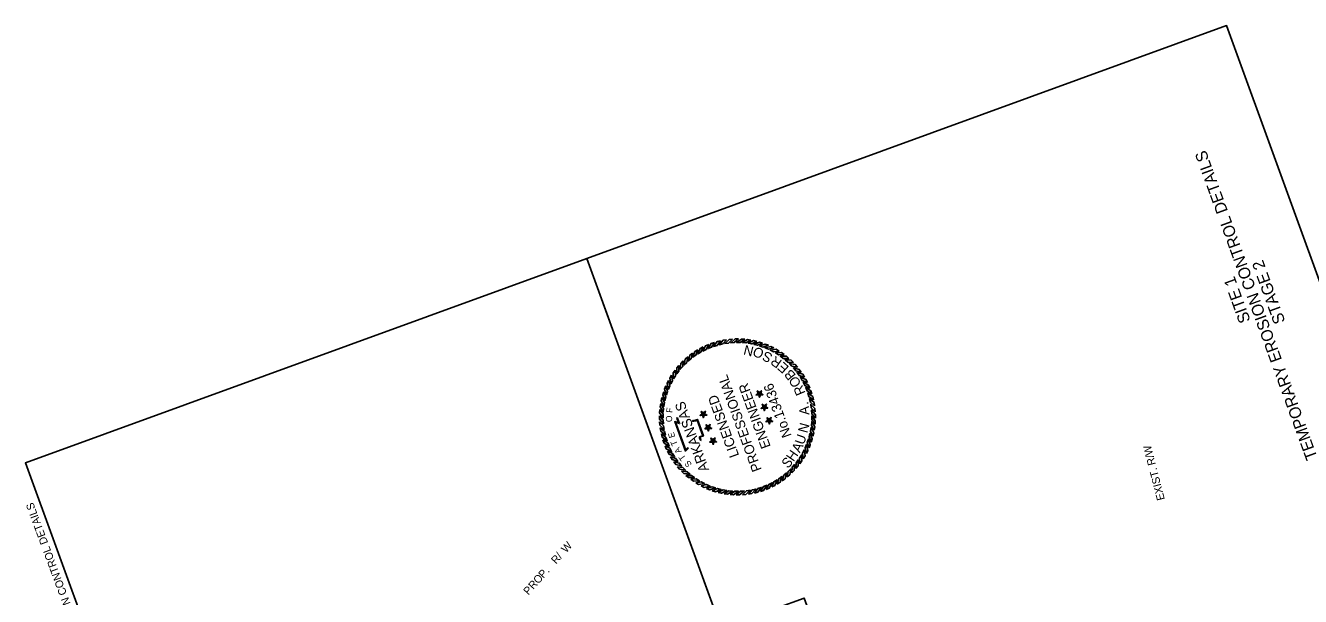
# Model space of a CAD drawing. Extents: x 986289 to 987754, y 1870781 to 1872971.
# Drawn here: x 986289 to 987265, y 1872534 to 1872971 of the extents above; entities that cross this region are included whole.
import ezdxf

# ---------------------------------------------------------------- set-up
doc = ezdxf.new("R2010")
doc.units = 0
for name, color, linetype in [('1', 7, 'Continuous'), ('60', 7, 'Continuous'), ('G-ANNO-SYMB', 7, 'Continuous'), ('NO PLOT', 7, 'Continuous'), ('R_Draft', 7, 'Continuous')]:
    doc.layers.add(name, color=color, linetype=linetype)

msp = doc.modelspace()

# ---------------------------------------------------------------- linework, layer by layer
at = {"layer": '1'}
msp.add_line((986821.23, 1872510.15), (986718.28, 1872792.99), dxfattribs=at)
at = {"layer": 'G-ANNO-SYMB'}
for points in [[(986820.6, 1872730.02), (986818.11, 1872729.41), (986815.39, 1872725.73), (986818.04, 1872726.56)], [(986825.21, 1872730.87), (986822.68, 1872730.45), (986819.68, 1872727), (986822.38, 1872727.61)], [(986829.87, 1872731.35), (986827.31, 1872731.13), (986824.05, 1872727.92), (986826.79, 1872728.32)], [(986834.55, 1872731.46), (986831.99, 1872731.44), (986828.48, 1872728.5), (986831.25, 1872728.69)], [(986839.23, 1872731.21), (986836.67, 1872731.39), (986832.95, 1872728.74), (986835.72, 1872728.7)], [(986843.87, 1872730.59), (986841.34, 1872730.97), (986837.42, 1872728.62), (986840.18, 1872728.36)], [(986848.45, 1872729.6), (986845.95, 1872730.19), (986841.86, 1872728.14), (986844.59, 1872727.68)], [(986799.32, 1872720.6), (986797.25, 1872719.07), (986796.14, 1872714.64), (986798.27, 1872716.41)], [(986803.25, 1872723.14), (986801.07, 1872721.78), (986799.62, 1872717.45), (986801.88, 1872719.05)], [(986807.37, 1872725.37), (986805.09, 1872724.19), (986803.31, 1872719.98), (986805.69, 1872721.4)], [(986811.65, 1872727.26), (986809.29, 1872726.27), (986807.18, 1872722.21), (986809.66, 1872723.44)], [(986816.07, 1872728.82), (986813.64, 1872728.01), (986811.22, 1872724.13), (986813.79, 1872725.16)], [(986852.94, 1872728.26), (986850.5, 1872729.04), (986846.26, 1872727.33), (986848.94, 1872726.65)], [(986857.31, 1872726.58), (986854.93, 1872727.54), (986850.57, 1872726.17), (986853.2, 1872725.28)], [(986861.54, 1872724.55), (986859.24, 1872725.7), (986854.79, 1872724.67), (986857.33, 1872723.58)], [(986865.59, 1872722.2), (986863.39, 1872723.53), (986858.87, 1872722.85), (986861.32, 1872721.56)], [(986869.44, 1872719.54), (986867.36, 1872721.03), (986862.8, 1872720.72), (986865.14, 1872719.24)], [(986788.88, 1872711.23), (986787.22, 1872709.27), (986787.18, 1872704.7), (986788.84, 1872706.92)], [(986792.11, 1872714.62), (986790.31, 1872712.8), (986789.91, 1872708.24), (986791.73, 1872710.33)], [(986795.59, 1872717.75), (986793.65, 1872716.07), (986792.9, 1872711.56), (986794.88, 1872713.5)], [(986873.08, 1872716.58), (986871.12, 1872718.24), (986866.54, 1872718.28), (986868.77, 1872716.62)], [(986876.47, 1872713.35), (986874.64, 1872715.16), (986870.09, 1872715.55), (986872.17, 1872713.73)], [(986879.6, 1872709.87), (986877.92, 1872711.81), (986873.41, 1872712.56), (986875.34, 1872710.58)], [(986783.26, 1872703.74), (986781.93, 1872701.55), (986782.61, 1872697.02), (986783.9, 1872699.48)], [(986785.92, 1872707.6), (986784.43, 1872705.51), (986784.75, 1872700.95), (986786.22, 1872703.3)], [(986882.44, 1872706.14), (986880.92, 1872708.21), (986876.48, 1872709.32), (986878.26, 1872707.19)], [(986884.98, 1872702.21), (986883.63, 1872704.39), (986879.29, 1872705.84), (986880.9, 1872703.58)], [(986887.21, 1872698.09), (986886.03, 1872700.37), (986881.82, 1872702.15), (986883.24, 1872699.77)], [(986777.2, 1872691.1), (986776.42, 1872688.65), (986778.13, 1872684.41), (986778.81, 1872687.1)], [(986778.89, 1872695.47), (986777.92, 1872693.09), (986779.29, 1872688.73), (986780.18, 1872691.35)], [(986780.91, 1872699.69), (986779.76, 1872697.4), (986780.79, 1872692.94), (986781.88, 1872695.49)], [(986850.53, 1872689.56), (986850.49, 1872690.6), (986848.85, 1872691.71), (986849.52, 1872689.84)], [(986850.53, 1872689.56), (986851.5, 1872689.91), (986852.05, 1872691.82), (986850.49, 1872690.6)], [(986889.11, 1872693.81), (986888.11, 1872696.17), (986884.06, 1872698.28), (986885.28, 1872695.8)], [(986890.66, 1872689.39), (986889.86, 1872691.82), (986885.98, 1872694.25), (986887.01, 1872691.67)], [(986774.88, 1872682.03), (986774.49, 1872679.49), (986776.85, 1872675.57), (986777.1, 1872678.33)], [(986775.86, 1872686.61), (986775.28, 1872684.11), (986777.32, 1872680.02), (986777.78, 1872682.75)], [(986850.53, 1872689.56), (986849.52, 1872689.84), (986847.96, 1872688.63), (986849.94, 1872688.69)], [(986850.53, 1872689.56), (986849.94, 1872688.69), (986850.62, 1872686.83), (986851.17, 1872688.74)], [(986850.53, 1872689.56), (986851.17, 1872688.74), (986853.15, 1872688.81), (986851.5, 1872689.91)], [(986854.26, 1872679.31), (986854.22, 1872680.35), (986852.58, 1872681.46), (986853.26, 1872679.59)], [(986854.26, 1872679.31), (986855.24, 1872679.66), (986855.78, 1872681.57), (986854.22, 1872680.35)], [(986891.87, 1872684.86), (986891.25, 1872687.35), (986887.58, 1872690.07), (986888.4, 1872687.42)], [(986892.71, 1872680.25), (986892.29, 1872682.78), (986888.84, 1872685.78), (986889.46, 1872683.08)], [(986893.19, 1872675.59), (986892.98, 1872678.15), (986889.77, 1872681.41), (986890.17, 1872678.67)], [(986774, 1872672.71), (986774.02, 1872670.14), (986776.96, 1872666.64), (986776.77, 1872669.4)], [(986774.26, 1872677.38), (986774.07, 1872674.82), (986776.73, 1872671.1), (986776.76, 1872673.87)], [(986807.6, 1872673.93), (986806.6, 1872674.22), (986805.04, 1872673), (986807.02, 1872673.07)], [(986807.6, 1872673.93), (986807.56, 1872674.97), (986805.92, 1872676.08), (986806.6, 1872674.22)], [(986807.6, 1872673.93), (986807.02, 1872673.07), (986807.69, 1872671.21), (986808.24, 1872673.11)], [(986807.6, 1872673.93), (986808.58, 1872674.29), (986809.12, 1872676.19), (986807.56, 1872674.97)], [(986807.6, 1872673.93), (986808.24, 1872673.11), (986810.22, 1872673.18), (986808.58, 1872674.29)], [(986854.26, 1872679.31), (986853.26, 1872679.59), (986851.69, 1872678.37), (986853.67, 1872678.44)], [(986854.26, 1872679.31), (986853.67, 1872678.44), (986854.35, 1872676.58), (986854.9, 1872678.49)], [(986854.26, 1872679.31), (986854.9, 1872678.49), (986856.88, 1872678.55), (986855.24, 1872679.66)], [(986893.31, 1872670.91), (986893.29, 1872673.48), (986890.35, 1872676.98), (986890.53, 1872674.21)], [(986893.05, 1872666.23), (986893.24, 1872668.79), (986890.58, 1872672.51), (986890.55, 1872669.74)], [(986774.11, 1872668.02), (986774.33, 1872665.47), (986777.54, 1872662.2), (986777.14, 1872664.95)], [(986774.59, 1872663.36), (986775.01, 1872660.83), (986778.46, 1872657.83), (986777.85, 1872660.53)], [(986811.33, 1872663.68), (986810.33, 1872663.97), (986808.77, 1872662.75), (986810.75, 1872662.82)], [(986811.33, 1872663.68), (986811.29, 1872664.72), (986809.65, 1872665.83), (986810.33, 1872663.97)], [(986811.33, 1872663.68), (986810.75, 1872662.82), (986811.42, 1872660.96), (986811.97, 1872662.86)], [(986811.33, 1872663.68), (986812.31, 1872664.04), (986812.85, 1872665.94), (986811.29, 1872664.72)], [(986811.33, 1872663.68), (986811.97, 1872662.86), (986813.95, 1872662.93), (986812.31, 1872664.04)], [(986857.99, 1872669.06), (986856.99, 1872669.34), (986855.43, 1872668.12), (986857.41, 1872668.19)], [(986857.99, 1872669.06), (986857.95, 1872670.1), (986856.31, 1872671.2), (986856.99, 1872669.34)], [(986857.99, 1872669.06), (986857.41, 1872668.19), (986858.08, 1872666.33), (986858.63, 1872668.23)], [(986857.99, 1872669.06), (986858.97, 1872669.41), (986859.51, 1872671.32), (986857.95, 1872670.1)], [(986857.99, 1872669.06), (986858.63, 1872668.23), (986860.61, 1872668.3), (986858.97, 1872669.41)], [(986891.45, 1872657.01), (986892.03, 1872659.51), (986889.99, 1872663.6), (986889.52, 1872660.87)], [(986892.43, 1872661.59), (986892.82, 1872664.13), (986890.46, 1872668.05), (986890.21, 1872665.28)], [(986775.44, 1872658.75), (986776.05, 1872656.26), (986779.73, 1872653.54), (986778.91, 1872656.19)], [(986776.64, 1872654.23), (986777.45, 1872651.79), (986781.33, 1872649.37), (986780.3, 1872651.94)], [(986815.06, 1872653.43), (986814.06, 1872653.72), (986812.5, 1872652.5), (986814.48, 1872652.57)], [(986815.06, 1872653.43), (986815.02, 1872654.47), (986813.38, 1872655.58), (986814.06, 1872653.72)], [(986815.06, 1872653.43), (986814.48, 1872652.57), (986815.16, 1872650.71), (986815.7, 1872652.61)], [(986815.06, 1872653.43), (986816.04, 1872653.79), (986816.59, 1872655.69), (986815.02, 1872654.47)], [(986815.06, 1872653.43), (986815.7, 1872652.61), (986817.68, 1872652.68), (986816.04, 1872653.79)], [(986888.42, 1872648.15), (986889.39, 1872650.53), (986888.01, 1872654.89), (986887.13, 1872652.26)], [(986890.11, 1872652.52), (986890.89, 1872654.97), (986889.17, 1872659.2), (986888.49, 1872656.52)], [(986778.2, 1872649.81), (986779.2, 1872647.45), (986783.25, 1872645.33), (986782.02, 1872647.82)], [(986780.1, 1872645.53), (986781.27, 1872643.25), (986785.48, 1872641.46), (986784.06, 1872643.84)], [(986881.39, 1872636.02), (986882.88, 1872638.1), (986882.56, 1872642.67), (986881.09, 1872640.32)], [(986884.05, 1872639.87), (986885.37, 1872642.07), (986884.7, 1872646.59), (986883.41, 1872644.14)], [(986886.4, 1872643.93), (986887.55, 1872646.22), (986886.52, 1872650.67), (986885.43, 1872648.13)], [(986782.32, 1872641.4), (986783.68, 1872639.23), (986788.01, 1872637.77), (986786.41, 1872640.04)], [(986784.87, 1872637.47), (986786.39, 1872635.41), (986790.82, 1872634.3), (986789.05, 1872636.43)], [(986787.71, 1872633.75), (986789.39, 1872631.81), (986793.9, 1872631.05), (986791.96, 1872633.04)], [(986875.2, 1872628.99), (986877, 1872630.82), (986877.4, 1872635.37), (986875.58, 1872633.29)], [(986878.43, 1872632.38), (986880.08, 1872634.35), (986880.12, 1872638.92), (986878.47, 1872636.69)], [(986790.84, 1872630.26), (986792.66, 1872628.46), (986797.22, 1872628.06), (986795.13, 1872629.89)], [(986794.23, 1872627.03), (986796.19, 1872625.38), (986800.76, 1872625.34), (986798.54, 1872626.99)], [(986797.86, 1872624.08), (986799.95, 1872622.58), (986804.51, 1872622.9), (986802.17, 1872624.38)], [(986859.94, 1872618.25), (986862.21, 1872619.43), (986864, 1872623.64), (986861.62, 1872622.22)], [(986864.06, 1872620.48), (986866.24, 1872621.83), (986867.69, 1872626.17), (986865.42, 1872624.56)], [(986867.99, 1872623.02), (986870.06, 1872624.54), (986871.16, 1872628.98), (986869.03, 1872627.2)], [(986871.71, 1872625.86), (986873.65, 1872627.54), (986874.41, 1872632.05), (986872.42, 1872630.12)], [(986801.72, 1872621.41), (986803.92, 1872620.09), (986808.44, 1872620.76), (986805.98, 1872622.05)], [(986805.77, 1872619.06), (986808.07, 1872617.91), (986812.52, 1872618.94), (986809.97, 1872620.03)], [(986810, 1872617.04), (986812.37, 1872616.07), (986816.73, 1872617.45), (986814.11, 1872618.34)], [(986814.37, 1872615.35), (986816.81, 1872614.57), (986821.05, 1872616.29), (986818.36, 1872616.97)], [(986818.86, 1872614.01), (986821.35, 1872613.43), (986825.45, 1872615.47), (986822.71, 1872615.94)], [(986823.44, 1872613.03), (986825.97, 1872612.64), (986829.89, 1872615), (986827.13, 1872615.25)], [(986828.08, 1872612.41), (986830.64, 1872612.22), (986834.36, 1872614.88), (986831.59, 1872614.91)], [(986832.76, 1872612.15), (986835.32, 1872612.17), (986838.82, 1872615.11), (986836.06, 1872614.93)], [(986837.44, 1872612.27), (986840, 1872612.49), (986843.26, 1872615.69), (986840.51, 1872615.29)], [(986842.1, 1872612.75), (986844.63, 1872613.17), (986847.63, 1872616.62), (986844.93, 1872616)], [(986846.71, 1872613.59), (986849.2, 1872614.21), (986851.92, 1872617.88), (986849.27, 1872617.06)], [(986851.23, 1872614.8), (986853.67, 1872615.61), (986856.09, 1872619.48), (986853.52, 1872618.45)], [(986855.65, 1872616.35), (986858.02, 1872617.35), (986860.13, 1872621.41), (986857.64, 1872620.18)]]:
    msp.add_lwpolyline(points, close=True, dxfattribs=at)
for points in [[(986795.97, 1872648.29), (986794.03, 1872646.37), (986786.26, 1872667.67), (986789.34, 1872666.65), (986788.47, 1872668.93), (986788, 1872670.18), (986787.68, 1872671.49)], [(986796.23, 1872648.02), (986793.88, 1872645.68), (986785.64, 1872668.29), (986788.7, 1872667.26), (986788.12, 1872668.79), (986787.63, 1872670.07), (986787.31, 1872671.4)], [(986799.06, 1872668.88), (986799.62, 1872668.55), (986800.28, 1872668.6), (986801.55, 1872668.91), (986802.78, 1872669.36), (986807.11, 1872657.45), (986805.36, 1872656.81), (986804.62, 1872656.55), (986804.67, 1872655.64), (986805.27, 1872653.98), (986805.03, 1872653.65)], [(986799.25, 1872669.21), (986799.71, 1872668.94), (986800.22, 1872668.98), (986801.44, 1872669.28), (986803, 1872669.85), (986807.6, 1872657.22), (986805.49, 1872656.46), (986805.02, 1872656.29), (986805.05, 1872655.72), (986805.7, 1872653.92), (986805.33, 1872653.42)]]:
    msp.add_lwpolyline(points, dxfattribs=at)
at = {"layer": 'NO PLOT'}
for points in [[(987753.66, 1871472.09), (987208.01, 1872971.24), (986718.28, 1872792.99), (986821.23, 1872510.15), (986884.66, 1872533.24), (987030.02, 1872133.87), (986966.59, 1872110.78), (987064.47, 1871841.86), (987122.5, 1871862.99), (987239.7, 1871540.99), (987181.66, 1871519.87), (987263.93, 1871293.85)], [(987753.66, 1871472.09), (987208.01, 1872971.24), (986718.28, 1872792.99), (986821.23, 1872510.15), (986884.66, 1872533.24), (987030.02, 1872133.87), (986966.59, 1872110.78), (987064.47, 1871841.86), (987122.5, 1871862.99), (987239.7, 1871540.99), (987181.66, 1871519.87), (987263.93, 1871293.85)], [(987753.66, 1871472.09), (987208.01, 1872971.24), (986718.28, 1872792.99), (986821.23, 1872510.15), (986884.66, 1872533.24), (987030.02, 1872133.87), (986966.59, 1872110.78), (987064.47, 1871841.86), (987122.5, 1871862.99), (987239.7, 1871540.99), (987181.66, 1871519.87), (987263.93, 1871293.85)], [(987753.66, 1871472.09), (987208.01, 1872971.24), (986718.28, 1872792.99), (986821.23, 1872510.15), (986884.66, 1872533.24), (987030.02, 1872133.87), (986966.59, 1872110.78), (987064.47, 1871841.86), (987122.5, 1871862.99), (987239.7, 1871540.99), (987181.66, 1871519.87), (987263.93, 1871293.85)], [(987753.66, 1871472.09), (987208.01, 1872971.24), (986718.28, 1872792.99), (986821.23, 1872510.15), (986884.66, 1872533.24), (987030.02, 1872133.87), (986966.59, 1872110.78), (987064.47, 1871841.86), (987122.5, 1871862.99), (987239.7, 1871540.99), (987181.66, 1871519.87), (987263.93, 1871293.85)], [(986774.2, 1871115.6), (986369.23, 1872228.25), (986415.65, 1872245.15), (986348.68, 1872429.14), (986362.4, 1872434.13), (986288.69, 1872636.64), (986718.28, 1872792.99), (986821.23, 1872510.15), (986748.87, 1872483.82), (986894.23, 1872084.45), (986966.59, 1872110.78), (987064.47, 1871841.86), (987008.75, 1871821.58), (987125.95, 1871499.59), (987181.66, 1871519.87), (987263.93, 1871293.85)], [(986774.2, 1871115.6), (986369.23, 1872228.25), (986415.65, 1872245.15), (986348.68, 1872429.14), (986362.4, 1872434.13), (986288.69, 1872636.64), (986718.28, 1872792.99), (986821.23, 1872510.15), (986748.87, 1872483.82), (986894.23, 1872084.45), (986966.59, 1872110.78), (987064.47, 1871841.86), (987008.75, 1871821.58), (987125.95, 1871499.59), (987181.66, 1871519.87), (987263.93, 1871293.85)], [(986774.2, 1871115.6), (986369.23, 1872228.25), (986415.65, 1872245.15), (986348.68, 1872429.14), (986362.4, 1872434.13), (986288.69, 1872636.64), (986718.28, 1872792.99), (986821.23, 1872510.15), (986748.87, 1872483.82), (986894.23, 1872084.45), (986966.59, 1872110.78), (987064.47, 1871841.86), (987008.75, 1871821.58), (987125.95, 1871499.59), (987181.66, 1871519.87), (987263.93, 1871293.85)], [(986774.2, 1871115.6), (986369.23, 1872228.25), (986415.65, 1872245.15), (986348.68, 1872429.14), (986362.4, 1872434.13), (986288.69, 1872636.64), (986718.28, 1872792.99), (986821.23, 1872510.15), (986748.87, 1872483.82), (986894.23, 1872084.45), (986966.59, 1872110.78), (987064.47, 1871841.86), (987008.75, 1871821.58), (987125.95, 1871499.59), (987181.66, 1871519.87), (987263.93, 1871293.85)], [(986774.2, 1871115.6), (986369.23, 1872228.25), (986415.65, 1872245.15), (986348.68, 1872429.14), (986362.4, 1872434.13), (986288.69, 1872636.64), (986718.28, 1872792.99), (986821.23, 1872510.15), (986748.87, 1872483.82), (986894.23, 1872084.45), (986966.59, 1872110.78), (987064.47, 1871841.86), (987008.75, 1871821.58), (987125.95, 1871499.59), (987181.66, 1871519.87), (987263.93, 1871293.85)]]:
    msp.add_lwpolyline(points, close=True, dxfattribs=at)

# ---------------------------------------------------------------- texts
at = {"layer": '1'}
msp.add_text('TEMPORARY EROSION CONTROL DETAILS', height=6, rotation=110.32307, dxfattribs=at).set_placement((986352.56, 1872450.06))
at = {"layer": '60'}
for s, p in [('TEMPORARY EROSION CONTROL DETAILS', (987277.82, 1872640.76)), ('STAGE 2', (987253.12, 1872744.82)), ('SITE 1', (987226.54, 1872745.48))]:
    msp.add_text(s, height=9, rotation=110, dxfattribs=at).set_placement(p)
at = {"layer": 'G-ANNO-SYMB'}
for s, height, rotation, p in [('N', 7.5, 166.10067, (986846.61, 1872725.2)), ('O', 7.5, 154.77573, (986854.74, 1872722.61)), ('S', 7.5, 153.48784, (986861.17, 1872719.47)), ('R', 7.5, 145.65967, (986868.32, 1872714.74)), ('E', 7.5, 137.83149, (986873.61, 1872709.91)), ('PROFESSIONAL', 7.5, 110, (986852.32, 1872631.47)), ('B', 7.5, 128.88501, (986878.75, 1872703.72)), ('O', 7.5, 121.42961, (986882.81, 1872697.2)), ('ENGINEER', 7.5, 110, (986859.22, 1872649.19)), ('No.13436', 7.47, 110, (986875.22, 1872657.53)), ('R', 7.5, 113.22866, (986885.89, 1872690.16)), ('ARKANSAS', 7.747, 110, (986812.1, 1872631.38)), ('LICENSED', 7.5, 110, (986835.04, 1872642.29)), ('.', 7.5, 101.30002, (986888.15, 1872681.19)), ('O', 4.75, 91.2218, (986783.7, 1872667.93)), ('F', 4.75, 85.36282, (986783.87, 1872674.8)), ('A', 7.5, 93.09908, (986888.62, 1872673.52)), ('N', 7.5, 74.93262, (986887.04, 1872659.03)), ('E', 4.75, 106.67203, (986786.11, 1872656.54)), ('T', 4.75, 111.47887, (986788.06, 1872650.78)), ('U', 7.5, 70.90262, (986884.38, 1872650.02)), ('A', 4.75, 118.67877, (986791.04, 1872645.35)), ('T', 4.75, 126.90148, (986794.43, 1872640.44)), ('H', 7.5, 55.61905, (986876.58, 1872637.14)), ('A', 7.5, 63.44722, (986881.38, 1872643.95)), ('S', 4.75, 129.77256, (986799.04, 1872635.7)), ('S', 7.5, 48.16364, (986872.22, 1872631.91))]:
    msp.add_text(s, height=height, rotation=rotation, dxfattribs=at).set_placement(p)
at = {"layer": 'R_Draft'}
for s, rotation, p in [('EXIST. R/W', 104.47173, (987160.8, 1872608.78)), ('W', 48.10538, (986702.54, 1872567.39)), ('R', 48.10538, (986694.85, 1872558.81)), ('/', 48.10538, (986698.63, 1872563.03)), ('P', 48.10538, (986685.1, 1872547.94)), ('R', 48.10538, (986677.4, 1872539.36)), ('O', 48.10538, (986681.19, 1872543.58)), ('.', 48.10538, (986688.88, 1872552.16)), ('P', 48.10538, (986673.62, 1872535.14))]:
    msp.add_text(s, height=6, rotation=rotation, dxfattribs=at).set_placement(p)

doc.saveas('drawing.dxf')
